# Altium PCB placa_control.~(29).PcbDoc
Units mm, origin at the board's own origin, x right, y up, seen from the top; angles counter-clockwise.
Board outline 56.95 x 119.37 mm, 2 copper layers (Top Layer, Bottom Layer); 35 components, 26 nets, 134 pads, 100 vias.
Unrouted connection lines stored in the file: 18.
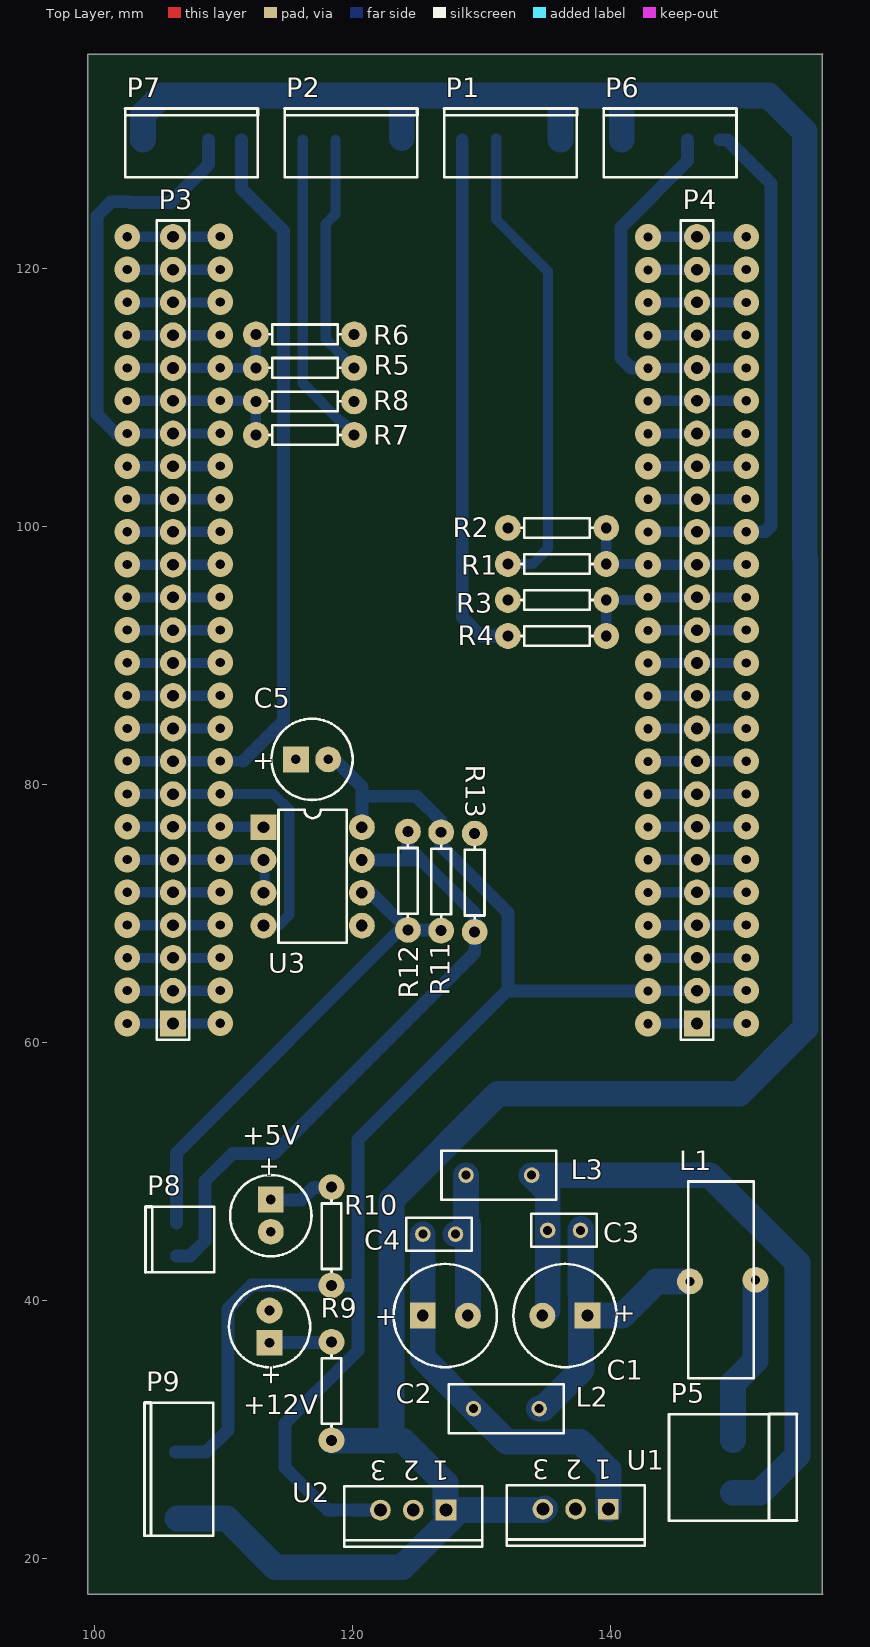
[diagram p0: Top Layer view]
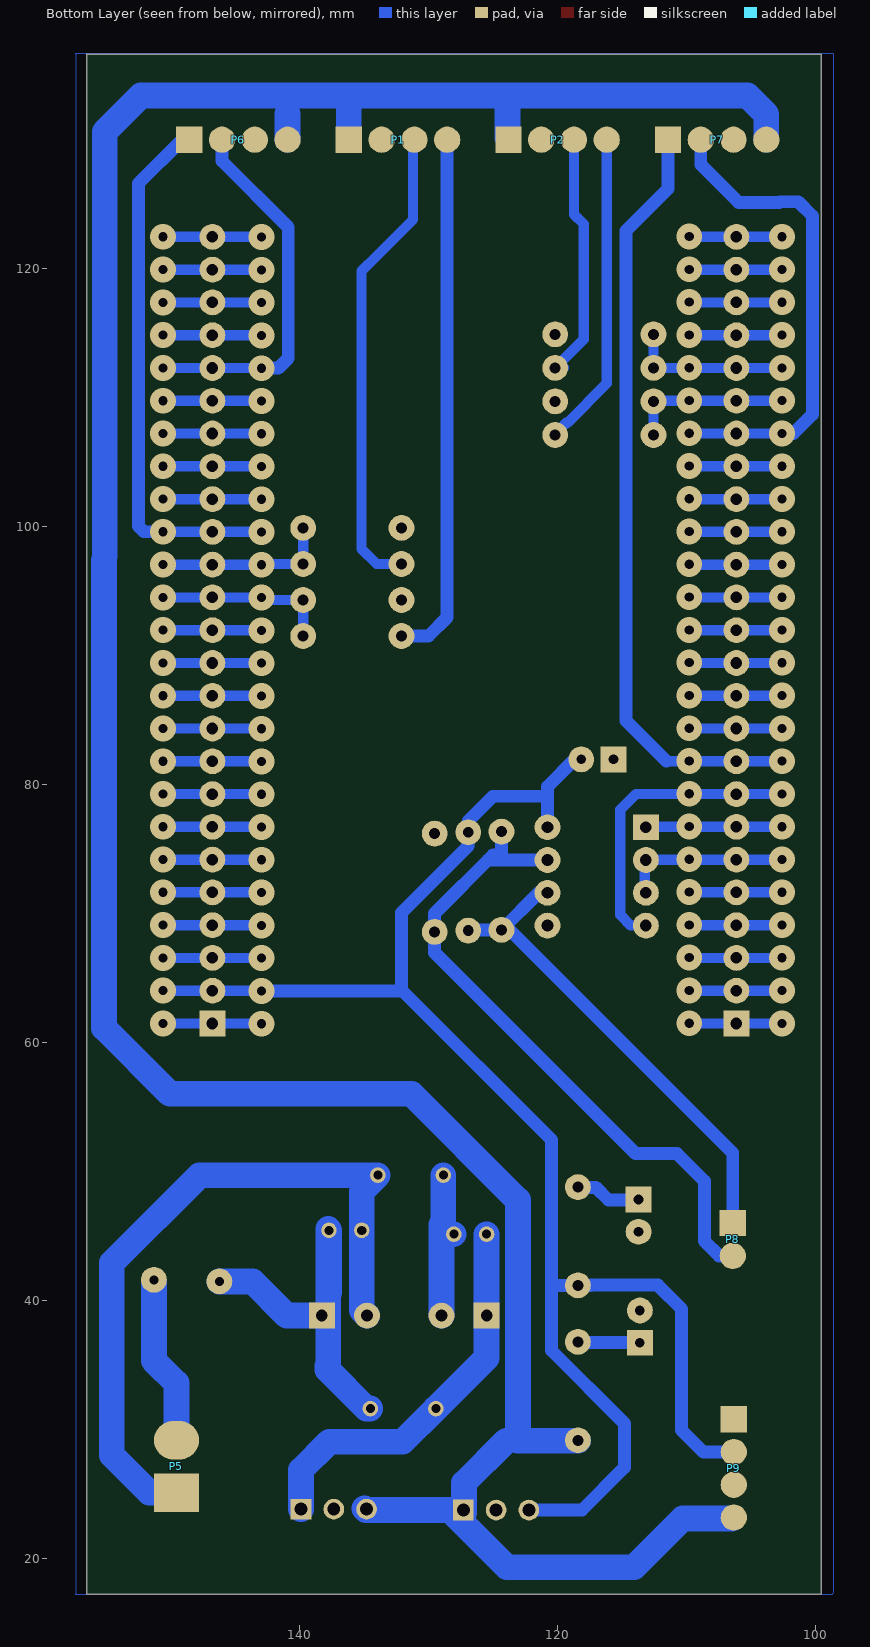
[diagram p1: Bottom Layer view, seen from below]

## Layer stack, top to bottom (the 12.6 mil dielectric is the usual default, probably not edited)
Top Layer: signal copper 0.0356
Dielectric: dielectric 0.32, FR-4, Dk 4.8
Bottom Layer: signal copper 0.0356

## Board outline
99.525,136.6 156.45,136.6 156.475,136.625 156.45,136.6 156.45,17.3 156.475,17.275 99.55,17.275 99.525,17.25

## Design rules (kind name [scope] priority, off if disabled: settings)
Clearance [All] p1: gap=0.4
ComponentClearance [All] p1: gap=0.254 collisioncheckmode=3 verticalgap=0.254
PlaneConnect [All] p1: planeconnectstyle=Relief reliefexpansion=0.508 reliefentries=4 reliefconductorwidth=0.6 reliefairgap=0.254
PolygonConnect [All] p1: connectstyle=Relief reliefconductorwidth=0.6 reliefentries=4 polygonreliefangle="90 Angle"
RoomDefinition REGULADOR [InComponentClass('REGULADOR')] p1: confinementstyle=ConfineIn formatcopy=TRUE lockcomponents=FALSE outline 99.475,17.575 155.697,17.575 155.697,54.2 99.475,54.2
RoomDefinition INTERFAZ [InComponentClass('INTERFAZ')] p2: confinementstyle=ConfineIn formatcopy=TRUE lockcomponents=FALSE outline 110.775,62.675 143.675,62.675 143.675,88.075 110.775,88.075
RoomDefinition ENCODER [InComponentClass('ENCODER')] p3: confinementstyle=ConfineOut formatcopy=TRUE lockcomponents=FALSE outline 141.4,147.25 141.4,152.45 116,152.45 116,147.25
RoomDefinition BOARD-ARM [InComponentClass('BOARD-ARM')] p4: confinementstyle=ConfineOut formatcopy=TRUE lockcomponents=FALSE outline 166.025,120.7 232.827,120.7 232.827,146.1 166.025,146.1
RoomDefinition placa_control_esquema [InComponentClass('placa_control_esquema')] p5: confinementstyle=ConfineIn formatcopy=TRUE lockcomponents=FALSE outline 99.5,17.3 156.425,17.3 156.425,136.625 99.5,136.625
RoutingVias [All] p1: holewidth=0.711 width=2 viastyle="Through Hole" minholewidth=0.711 minwidth=1.27 maxholewidth=0.711 maxwidth=2
SolderMaskExpansion [All] p1: expansion=0.102
TestPointUsage [All] p1: valid=0 allowmultiple=FALSE
Testpoint [All] p1: side=15 testpointundercomponent=TRUE minsize=1.016 maxsize=2.54 preferedsize=1.524 minholesize=0 maxholesize=1.016 preferedholesize=0.813 testpointgrid=0.025 style=1023 order=0-112345678
Width [All] p1: maxlimit=2 minlimit=0.8 preferedwidth=0.8
17 further rules are at their usual default settings.

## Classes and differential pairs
component class INTERFAZ: C5 P8 R11 R12 R13 U3
component class ENCODER: P1 P2 R1 R2 R3 R4 R5 R6 R7 R8
component class BOARD-ARM: P3 P4
component class REGULADOR: +5V +12V C1 C2 C3 C4 L1 L2 L3 P5 R9 R10 U1 U2
component class placa_control_esquema: P6 P7 P9

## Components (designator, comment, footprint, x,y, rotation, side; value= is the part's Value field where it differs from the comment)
+5V "LED2" CAPPR2.5-6.3X5 113.7,46.6 r270 top (schematic designator VCC2)
+12V "LED2" CAPPR2.5-6.3X5 113.6,38 r90 top (schematic designator VCC1)
C1 "Cap Pol3" CAPPR3.5-8X15 136.495,38.855 r180 top
C2 "Cap Pol3" CAPPR3.5-8X15 127.224,38.855 r0 top
C3 "Cap" RAD-0.1 136.424,45.464 r0 top
C4 "Cap" RAD-0.1 126.747,45.159 r180 top
C5 "Cap" CAPPR2.5-6.3X5 116.894,81.958 r0 top
L1 "Inductor Iron" bobina_Choque 151.137,39.085 r90 top
L2 "Inductor" RAD-0.2 131.949,31.641 r180 top
L3 "Inductor" RAD-0.2 131.369,49.731 r180 top
P1 "Header 4" HDR1X5 128.533,137.6 r180 top
P2 "Header 4" HDR1X5 116.167,137.6 r180 top
P3 "Header 25" HDR1X25 106.115,61.49 r90 top
P4 "Header 25" HDR1X25 146.73,61.49 r90 top
P5 "Header 2" pwheader1x2 149.514,27.285 r90 top
P6 "Header 4" HDR1X5 140.9,137.6 r180 top
P7 "Header 4" HDR1X5 103.8,137.6 r180 top
P8 "Header 2" wf2s 106.4,38.4 r270 top
P9 "Header 4" HDR1X5 98.7,23.2 r270 top
R1 "metal film 2%" AXIAL-0.3 135.884,97.102 r180 top
R2 "metal film 2%" AXIAL-0.3 135.884,99.894 r0 top
R3 "metal film 2%" AXIAL-0.3 135.884,91.518 r180 top
R4 "metal film 2%" AXIAL-0.3 135.884,94.31 r0 top
R5 "metal film 2%" AXIAL-0.3 116.35,112.3 r0 top
R6 "metal film 2%" AXIAL-0.3 116.35,114.9 r180 top
R7 "metal film 2%" AXIAL-0.3 116.35,107.1 r0 top
R8 "metal film 2%" AXIAL-0.3 116.35,109.7 r180 top
R9 "Carbon 1/8w 5%" AXIAL-0.3 118.4,33 r270 top
R10 "Carbon 1/8w 5%" AXIAL-0.3 118.4,45 r270 top
R11 "Carbon 1/8w 5%" AXIAL-0.3 126.9,72.5 r90 top
R12 "Carbon 1/8w 5%" AXIAL-0.3 124.326,72.55 r270 top
R13 "Carbon 1/8w 5%" AXIAL-0.3 129.5,72.4 r270 top
U1 "LM78L12ACZ" T03B 137.32,23.851 r180 top
U2 "LM78L05ACZ" T03B 124.738,23.785 r180 top
U3 "SN75176BP" 626-05 116.944,72.89 r270 top

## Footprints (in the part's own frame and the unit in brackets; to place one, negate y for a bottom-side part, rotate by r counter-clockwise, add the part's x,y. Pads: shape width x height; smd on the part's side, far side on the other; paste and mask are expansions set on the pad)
626-05 [mm] "DIP; 8 Leads; Row Spacing 7.62 mm; Pitch 2.54 mm"
  rect 2x2 hole 0.9: 1(-3.81,-3.81)
  round 2 hole 0.9: 2(-1.27,-3.81) 3(1.27,-3.81) 4(3.81,-3.81) 5(3.81,3.81) 6(1.27,3.81) 7(-1.27,3.81) 8(-3.81,3.81)
  silkscreen extent -5.15,-2.65 5.15,2.65
AXIAL-0.3 [mm] "Resistor; 2 Leads"
  round 2 hole 0.85: 1(-3.81,0) 2(3.81,0)
  silkscreen extent -2.77,-0.76 2.77,0.76
bobina_Choque [mm]
  round 2 hole 0.7: 1(2.54,-0.127) 2(2.413,4.953)
  silkscreen extent -5.08,0 10.16,5.08
CAPPR2.5-6.3X5 [mm] "Capacitor, Electrolytic, Radial; Body 6.3 x 5 mm (Dia.xH typ); Pin Spacing 2.5 mm (typ)"
  rect 2x2 hole 0.75: 1(-1.25,0)
  round 2 hole 0.75: 2(1.25,0)
  silkscreen extent -3.15,-3.15 3.15,3.15
CAPPR3.5-8X15 [mm] "Capacitor, Electrolytic, Radial; Body 8 x 15 mm (Dia.xH typ); Pin Spacing 3.5 mm (typ)"
  rect 2x2 hole 0.9: 1(-1.75,0)
  round 2 hole 0.9: 2(1.75,0)
  silkscreen extent -4,-4 4,4
HDR1X5 [mil]
  rect 80x80 smd far side: 1(-300,300)
  round 80 smd far side: 2(-200,300) 3(-100,300) 4(0,300)
  silkscreen extent -350,205 55,415
HDR1X25 [mm] "Connector; Header; 25 Position"
  rect 2x2 hole 0.9: 1(0,0)
  round 2 hole 0.9: 2(2.54,0) 3(5.08,0) 4(7.62,0) 5(10.16,0) 6(12.7,0) 7(15.24,0) 8(17.78,0) 9(20.32,0) 10(22.86,0) 11(25.4,0) 12(27.94,0) 13(30.48,0) 14(33.02,0) 15(35.56,0) 16(38.1,0) 17(40.64,0) 18(43.18,0) 19(45.72,0) 20(48.26,0) 21(50.8,0) 22(53.34,0) 23(55.88,0) 24(58.42,0) 25(60.96,0)
  silkscreen extent -1.27,-1.27 62.23,1.27
pwheader1x2 [mm]
  rect 3x3.5 smd far side: 1(-2.159,0)
  oval 3x3.5 smd far side: 2(1.905,0)
  silkscreen extent -4.32,-4.95 3.94,4.95
RAD-0.1 [mm] "Indicating Instrument; 2 Leads"
  round 1.2 hole 0.7: 1(-1.27,0) 2(1.27,0)
  silkscreen extent -2.54,-1.27 2.54,1.27
RAD-0.2 [mm] "Jumper Wire; 2 Leads"
  round 1.2 hole 0.7: 1(-2.54,0) 2(2.54,0)
  silkscreen extent -4.44,-1.91 4.44,1.91
T03B [mm] "TO, Thru-Hole, Vertical, Heatsink Mounted; 3 In-Line Leads; Pitch 2.54 mm"
  rect 1.6x1.6 hole 1: 1(-2.54,0)
  round 1.6 hole 1: 2(0,0) 3(2.54,0)
  silkscreen extent -5.35,-1.85 5.35,2.85
wf2s [mil]
  rect 80x80 smd far side: 1(-300,0)
  round 80 smd far side: 2(-200,0)
  silkscreen extent -350,-95 -150,115

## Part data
+5V +12V: "Typical RED, GREEN, YELLOW, AMBER GaAs LED"
C1: "Polarized Capacitor (Surface Mount)"
C2: "Polarized Capacitor 35V"
C3 C4 C5: "Capacitor"
L1: "Magnetic-Core Inductor"
P1 P2 P6 P7 P9: "Header, 4-Pin"
P3 P4: "Header, 25-Pin"
P5 P8: "Header, 2-Pin"
R1 R2 R3 R4 R5 R6 R7 R8 R9 R10 R11 R12 R13: library part "Res Semi", "Semiconductor Resistor"
U1 U2: "3-Terminal Positive Regulator"
U3: "Differential Bus Transceiver"

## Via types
v1: diameter 2, hole 0.711, Top Layer to Bottom Layer, 100 vias

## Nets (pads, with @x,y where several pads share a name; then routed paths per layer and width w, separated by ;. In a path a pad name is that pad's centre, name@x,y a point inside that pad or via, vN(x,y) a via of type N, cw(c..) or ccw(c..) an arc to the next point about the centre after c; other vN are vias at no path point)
+5V: C5.2 P4.2 P9.2 R10.2 R11.2 U2.3 U3.8 | length 123.5
  Bottom Layer w0.8: v1@143.23,64.03 v1@150.415,64.03
  Bottom Layer w1: P9.2 108.68,28.28 110.375,29.975 110.375,39.375 112.208,41.208 117.366,41.208 117.4,41.173 ; R10.2@118.4,41.173 120.45,41.173 ; C5.2@118.642,81.958 120.754,79.846 U3.8 U3.8@120.975,76.7 ; 120.754,79.1 124.975,79.1 126.9,77.175 126.9,75.25 132.075,70.075 132.075,64.015 ; U2.3 118.09,23.785 114.8,27.075 114.8,30.5 120.45,36.15 120.45,52.475 131.99,64.015 v1@142.915,64.015
  other v1: 142.925,64.015 150.55,64.035
+12V: P1.1 P2.1 P6.4 P7.4 P9.4 R9.2 U1.3 U2.1 | length 232.5
  Bottom Layer w2: P7.4 103.8,131.95 105.25,133.4 152.275,133.4 155.075,130.6 155.075,97.675 ; P9.4@106.475,23.125 110.275,23.125 114.05,19.35 123.9,19.35 128.335,23.785 134.832,23.785 U1.3@134.947,23.9 ; R9.2@118.4,29.159 123.053,29.159 123.053,47.803 131.3,56.05 150.025,56.05 155.125,61.15 155.125,97.375 ; 123.825,133.4 123.85,133.375 P2.1@123.85,130.1 ; 123.941,29.159 127.225,25.875 U2.1@127.225,23.6 ; P1.1 136.153,133.203 136.175,133.225 ; P6.4 140.9,131.975
GND: +5V.2 +12V.2 C2.2 C4.1 C5.1 L3.2 P1.2 P2.2 P4.1 P6.3 P7.3 P9.1 P9.3 R2.1 R4.1 R6.1 R8.1 R13.1 U1.2 U2.2 U3.5 | length 19
  Bottom Layer w0.8: v1@143.23,61.49 v1@150.415,61.49
  Bottom Layer w2: C4.1 128.934,45.159 ; L3.2 128.829,46.032 128.974,45.888 C2.2
  other v1: 142.925,61.475 150.55,61.495
IN_SD_1: P4.21 P6.2 | length 28.6
  Bottom Layer w0.8: v1@143.23,112.29 v1@150.415,112.29
  Bottom Layer w1: v1(142.925,112.275) 141.625,112.275 140.85,113.05 140.85,123.2 145.98,128.33 P6.2
  other v1: 150.55,112.295
IN_SD_2: P3.19 P7.2 | length 37.8
  Bottom Layer w0.8: v1@102.615,107.21 v1@109.8,107.21
  Bottom Layer w1: v1(102.575,107.22) 101.705,107.22 100.225,108.7 100.225,124.075 101.325,125.175 102.75,125.175 102.8,125.125 105.95,125.125 108.88,128.055 P7.2
  other v1: 109.775,107.235
NetC1_1: C1.1 C3.2 L1.2 L2.1 | length 29.3
  Bottom Layer w2: L2.1 134.788,31.641 137.797,34.65 137.797,34.95 137.747,35 C3.2@137.747,45.575 ; 137.694,40.65 C3.2 ; C1.1 140.952,38.855 143.595,41.498 L1.2
NetC1_2: C1.2 C3.1 L3.1 P5.1 | length 56.1
  Bottom Layer w2: C1.2 135.154,39.264 135.154,48.487 L3.1 147.716,49.731 154.522,42.925 154.522,28.05 151.598,25.126 P5.1
NetC2_1: C2.1 C4.2 L2.2 U1.1 | length 30.6
  Bottom Layer w2: C4.2 125.477,35.573 L2.2 129.431,31.641 131.997,29.075 137.672,29.075 139.86,26.887 U1.1
NetL1_1: L1.1 P5.2 | length 13.2
  Bottom Layer w0.8: L1.1@151.264,41.467 L1.1
  Bottom Layer w2: P5.2 149.514,33.617 151.264,35.367 L1.1@151.264,41.467
NetP1_3: P1.3 R1.2 | length 37
  Bottom Layer w0.8: P1.3@131.175,130.05 131.175,123.8 134.05,120.925 134.05,120.9 135.175,119.775 135.175,98.275 134.002,97.102 R1.2
NetP1_4: P1.4 R3.2 | length 41.2
  Bottom Layer w1: P1.4 128.533,92.967 129.982,91.518 R3.2
NetP2_3: P2.3 R5.2 | length 19.6
  Bottom Layer w0.8: P2.3 118.707,124.207 117.948,123.448 117.948,114.512 R5.2 R5.2@119.5,112.3
NetP2_4: P2.4 R7.2 | length 24.7
  Bottom Layer w0.8: P2.4 116.167,111.093 119.204,108.056 119.319,108.056 R7.2@120.325,107.05
NetP3_6: P3.6 U3.2 U3.3 | length 13.3
  Bottom Layer w0.8: v1@102.615,74.19 U3.2@113.21,74.19 ; U3.3 113.21,71.695 U3.2@113.21,74.19 ; U3.2@113.25,74.15 U3.2@113.21,74.19
  other v1: 102.575,74.2 109.775,74.215
NetP3_7: P3.7 U3.1 | length 10.5
  Bottom Layer w0.8: v1@102.615,76.73 U3.1@113.104,76.73
  other v1: 102.575,76.74 109.775,76.755
NetP3_8: P3.8 U3.4 | length 23.5
  Bottom Layer w0.8: v1@102.615,79.27 113.905,79.27 115.125,78.05 115.125,69.9 114.305,69.08 U3.4
  other v1: 102.575,79.28 109.775,79.295
NetP3_20: P3.20 R7.1 R8.2 | length 12.5
  Bottom Layer w0.8: v1@102.615,109.75 112.49,109.75 R8.2 R7.1
  other v1: 102.575,109.76 109.775,109.775
NetP3_21: P3.21 R5.1 R6.2 | length 12.6
  Bottom Layer w0.8: v1@102.615,112.29 112.53,112.29 R5.1@112.5,112.32 ; R5.1 R6.2
  other v1: 102.575,112.3 109.775,112.315
NetP4_14: P4.14 R3.1 R4.2 | length 13
  Bottom Layer w0.8: R3.1 R4.2 v1@142.74,94.31 ; v1@143.23,94.51 v1@150.415,94.51
  other v1: 142.925,94.495 150.55,94.515
NetP4_15: P4.15 R1.1 R2.2 | length 13.1
  Bottom Layer w0.8: R2.2 R1.1 v1@142.858,97.102 ; v1@143.23,97.05 v1@150.415,97.05
  other v1: 142.925,97.035 150.55,97.055
NetP8_1: P8.1 R11.1 R12.2 U3.6 | length 38.2
  Bottom Layer w1: P8.1 106.4,51.45 123.95,69 R12.2@124.2,69 ; U3.6 121.446,71.62 R12.2 ; R12.2@124.326,69.126 R12.2 ; R11.1 126.85,68.74 R12.2
NetP8_2: P8.2 R12.1 R13.2 U3.7 | length 52.1
  Bottom Layer w1: P8.2 107.455,43.48 108.6,44.625 108.6,49.275 110.725,51.4 113.925,51.4 129.5,66.975 129.5,70.025 124.976,74.549 124.326,74.549 R12.1 R12.1@124.366,76.4 ; U3.7 125.365,74.16
NetR9_1: +12V.1 R9.1 | length 3.8
  Bottom Layer w1: +12V.1@114.579,36.774 R9.1@118.4,36.774
NetR10_1: +5V.1 R10.1 | length 4.2
  Bottom Layer w1: 114.783,47.808 116.033,47.808 117.018,48.793 R10.1@118.55,48.793
PWM_1: P4.16 P6.1 | length 41.1
  Bottom Layer w0.8: v1@143.23,99.59 v1@150.415,99.59
  Bottom Layer w1: P6.1 149.07,129.98 152.45,126.6 152.45,100.025 152.025,99.6 v1@150.65,99.6
  other v1: 142.925,99.575 150.55,99.595
PWM_2: P3.9 P7.1 | length 59.7
  Bottom Layer w0.8: v1@102.615,81.81 111.535,81.81
  Bottom Layer w1: P7.1 111.42,126.18 114.675,122.925 114.675,84.95 111.535,81.81
  other v1: 102.575,81.82 109.775,81.835
pads on no net: P3.1 P3.2 P3.3 P3.4 P3.5 P3.10 P3.11 P3.12 P3.13 P3.14 P3.15 P3.16 P3.17 P3.18 P3.22 P3.23 P3.24 P3.25 P4.3 P4.4 P4.5 P4.6 P4.7 P4.8 P4.9 P4.10 P4.11 P4.12 P4.13 P4.17 P4.18 P4.19 P4.20 P4.22 P4.23 P4.24 P4.25
copper on no net: | length 265.8
  Bottom Layer w0.8: v1@102.615,61.49 v1@109.8,61.49 ; v1@102.615,64.03 v1@109.8,64.03 ; v1@102.615,66.57 v1@109.8,66.57 ; v1@102.615,69.11 v1@109.8,69.11 ; v1@102.615,71.65 v1@109.8,71.65 ; v1@102.615,84.35 v1@109.8,84.35 ; v1@102.615,86.89 v1@109.8,86.89 ; v1@102.615,89.43 v1@109.8,89.43 ; v1@102.615,91.97 v1@109.8,91.97 ; v1@102.615,94.51 v1@109.8,94.51 ; v1@102.615,97.05 v1@109.8,97.05 ; v1@102.615,99.59 v1@109.8,99.59 ; v1@102.615,102.13 v1@109.8,102.13 ; v1@102.615,104.67 v1@109.8,104.67 ; v1@102.615,114.83 v1@109.8,114.83 ; v1@102.615,117.37 v1@109.8,117.37 ; v1@102.615,119.91 v1@109.8,119.91 ; v1@102.615,122.45 v1@109.8,122.45 ; v1@143.23,66.57 v1@150.415,66.57 ; v1@143.23,69.11 v1@150.415,69.11 ; v1@143.23,71.65 v1@150.415,71.65 ; v1@143.23,74.19 v1@150.415,74.19 ; v1@143.23,76.73 v1@150.415,76.73 ; v1@143.23,79.27 v1@150.415,79.27 ; v1@143.23,81.81 v1@150.415,81.81 ; v1@143.23,84.35 v1@150.415,84.35 ; v1@143.23,86.89 v1@150.415,86.89 ; v1@143.23,89.43 v1@150.415,89.43 ; v1@143.23,91.97 v1@150.415,91.97 ; v1@143.23,102.13 v1@150.415,102.13 ; v1@143.23,104.67 v1@150.415,104.67 ; v1@143.23,107.21 v1@150.415,107.21 ; v1@143.23,109.75 v1@150.415,109.75 ; v1@143.23,114.83 v1@150.415,114.83 ; v1@143.23,117.37 v1@150.415,117.37 ; v1@143.23,119.91 v1@150.415,119.91 ; v1@143.23,122.45 v1@150.415,122.45
  other v1: 102.575,61.5 109.775,61.515 102.575,64.04 109.775,64.055 142.925,66.555 102.575,66.58 150.55,66.575 109.775,66.595 142.925,69.095 102.575,69.12 150.55,69.115 109.775,69.135 142.925,71.635 102.575,71.66 150.55,71.655 109.775,71.675 142.925,74.175 150.55,74.195 142.925,76.715 150.55,76.735 142.925,79.255 150.55,79.275 142.925,81.795 150.55,81.815 142.925,84.335 102.575,84.36 150.55,84.355 109.775,84.375 142.925,86.875 102.575,86.9 150.55,86.895 109.775,86.915 142.925,89.415 102.575,89.44 150.55,89.435 109.775,89.455 142.925,91.955 102.575,91.98 150.55,91.975 109.775,91.995 102.575,94.52 109.775,94.535 102.575,97.06 109.775,97.075 102.575,99.6 109.775,99.615 142.925,102.115 102.575,102.14 150.55,102.135 109.775,102.155 142.925,104.655 102.575,104.68 150.55,104.675 109.775,104.695 142.925,107.195 150.55,107.215 142.925,109.735 150.55,109.755 142.925,114.815 102.575,114.84 150.55,114.835 109.775,114.855 142.925,117.355 102.575,117.38 150.55,117.375 109.775,117.395 142.925,119.895 102.575,119.92 150.55,119.915 109.775,119.935 142.925,122.435 102.575,122.46 150.55,122.455 109.775,122.475

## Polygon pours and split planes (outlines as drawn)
GND on Bottom Layer "plano_señal_fuerte" (solid, remove dead copper, shelved, pour order 1000): 98.575,136.6 98.627,136.65 157.35,136.65 157.324,136.625 157.324,17.3 157.35,17.275 98.704,17.275 98.627,17.35 98.575,17.4

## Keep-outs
Drill Guide:
  rectangle: 103.975,54.175 149.375,124.375

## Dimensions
145.906,143.55 to 105.306,142.325 on Top Layer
